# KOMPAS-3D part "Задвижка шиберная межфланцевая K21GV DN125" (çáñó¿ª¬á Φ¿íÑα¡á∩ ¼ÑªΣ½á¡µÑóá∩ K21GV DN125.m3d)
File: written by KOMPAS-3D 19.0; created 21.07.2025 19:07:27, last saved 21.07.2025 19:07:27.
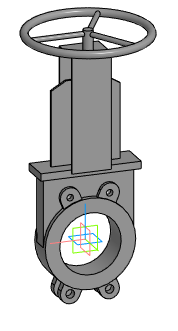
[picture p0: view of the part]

Document properties: Автор: Евгений; Полное имя файла: E:\Dendor Работа Сачек\3D для проектировщиков\2.3 Тип K21GV. Задвижка шиберная межфланцевая\stp_Задвижка шиберная K21GV DN50-400 с маховиком\Задвижка шиберная межфланцевая K21GV DN125.m3d

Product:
- Part/product: Задвижка шиберная межфланцевая K21GV DN125

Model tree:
1. Операция без истории:1  (labels: Задвижка шиберная межфланцевая K21GV DN125)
